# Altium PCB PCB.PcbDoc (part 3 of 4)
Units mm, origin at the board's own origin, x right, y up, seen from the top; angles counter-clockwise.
Board outline 430 x 130 mm, 2 copper layers (Top Layer, Bottom Layer); 471 components, 267 nets, 1806 pads, 471 vias.
Unrouted connection lines stored in the file: 127.
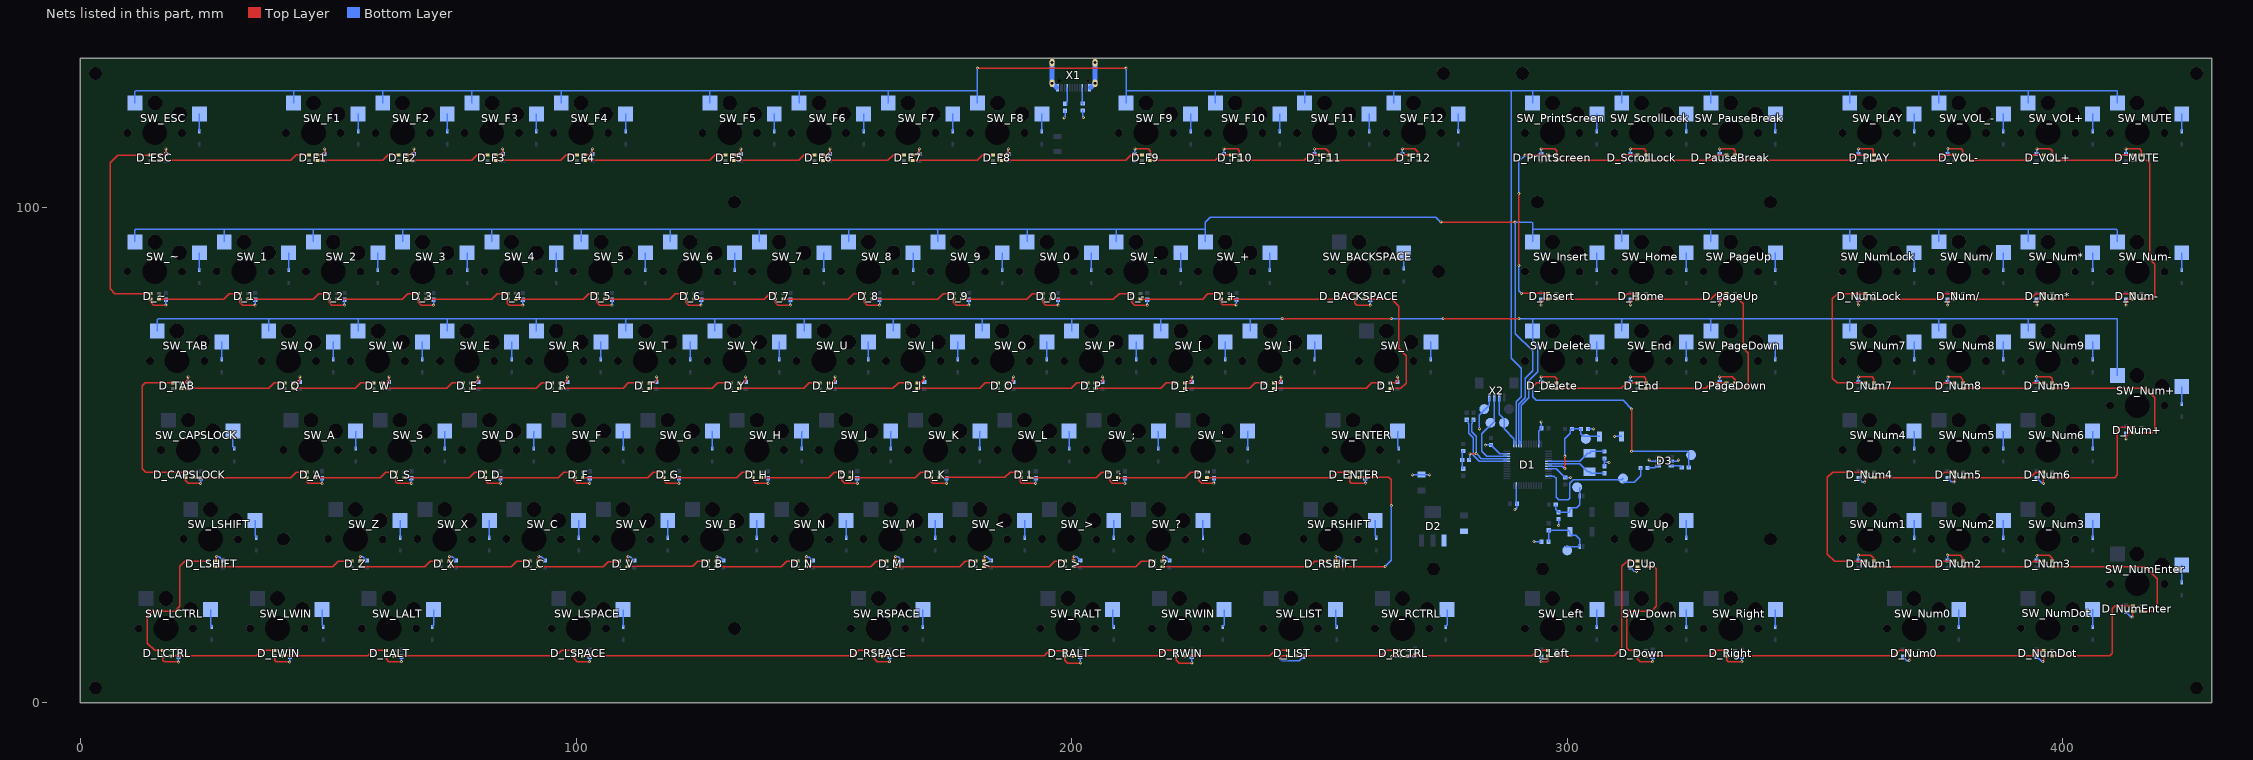
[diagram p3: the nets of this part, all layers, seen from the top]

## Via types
v1: diameter 0.6, hole 0.3, Top Layer to Bottom Layer, tented both sides, 471 vias

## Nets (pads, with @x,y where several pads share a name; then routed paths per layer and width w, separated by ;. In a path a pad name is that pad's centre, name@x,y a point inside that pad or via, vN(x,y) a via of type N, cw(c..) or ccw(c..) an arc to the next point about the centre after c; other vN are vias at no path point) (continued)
GND: C1.1 C2.1 C3.1 C4.1 C5.1 C6.1 C7.2 C8.2 C9.1 C10.1 C11.1 C12.1 C13.1 C14.1 C15.1 C16.1 C17.1 C18.1 C19.1 C20.1 C21.1 C22.1 C23.1 C24.1 C25.1 C26.1 C27.1 C28.1 C29.1 C30.1 C31.1 C32.1 C33.1 C34.1 C35.1 C36.1 C37.1 C38.1 C39.1 C40.1 C41.1 C42.1 C43.1 C44.1 C45.1 C46.1 C47.1 C48.1 C49.1 C50.1 C51.1 C52.1 C53.1 C54.1 C55.1 C56.1 C57.1 C58.1 C59.1 C60.1 C61.1 C62.1 C63.1 C64.1 C65.1 C66.1 C67.1 C68.1 C69.1 C70.1 C71.1 C72.1 C73.1 C74.1 C75.1 C76.1 C77.1 C78.1 C79.1 C80.1 C81.1 C82.1 C83.1 C84.1 C85.1 C86.1 C87.1 C88.1 C89.1 C90.1 C91.1 C92.1 C93.1 C94.1 C95.1 C96.1 C97.1 C98.1 C99.1 C100.1 C101.1 C102.1 C103.1 C104.1 C105.1 C106.1 C107.1 C108.1 C109.1 C110.1 C111.1 C112.1 C113.1 C114.1 C115.1 C116.1 C117.1 C118.1 D1.8 D1.23 D1.35 D1.47 D2.1 D3.2 D3.5 D_0.2 D_1.2 D_2.2 D_3.2 D_4.2 D_5.2 D_6.2 D_7.2 D_8.2 D_9.2 D_'.2 D_+.2 D_-.2 D_;.2 D_<.2 D_>.2 D_?.2 D_[.2 D_\.2 D_].2 D_A.2 D_B.2 D_BACKSPACE.2 D_C.2 D_CAPSLOCK.2 D_D.2 D_Delete.2 D_Down.2 D_E.2 D_End.2 D_ENTER.2 D_ESC.2 D_F1.2 D_F2.2 D_F3.2 D_F4.2 D_F5.2 D_F6.2 D_F7.2 D_F8.2 D_F9.2 D_F10.2 D_F11.2 D_F12.2 D_F.2 D_G.2 D_H.2 D_Home.2 D_I.2 D_Insert.2 D_J.2 D_K.2 D_L.2 D_LALT.2 D_LCTRL.2 D_Left.2 D_LIST.2 D_LSHIFT.2 D_LSPACE.2 D_LWIN.2 D_M.2 D_MUTE.2 D_N.2 D_Num0.2 D_Num1.2 D_Num2.2 D_Num3.2 D_Num4.2 D_Num5.2 D_Num6.2 D_Num7.2 D_Num8.2 D_Num9.2 D_Num*.2 D_Num+.2 D_Num-.2 D_Num/.2 D_NumDot.2 D_NumEnter.2 D_NumLock.2 D_O.2 D_P.2 D_PageDown.2 D_PageUp.2 D_PauseBreak.2 D_PLAY.2 D_PrintScreen.2 D_Q.2 D_R.2 D_RALT.2 D_RCTRL.2 D_Right.2 D_RSHIFT.2 D_RSPACE.2 D_RWIN.2 D_S.2 D_ScrollLock.2 D_T.2 D_TAB.2 D_U.2 D_Up.2 D_V.2 D_VOL+.2 D_VOL-.2 D_W.2 D_X.2 D_Y.2 D_Z.2 D_~.2 pad.3@283.25,59.25 R1.1 R2.1 R10.2 R11.2 SW3.2 X1.GND1 X1.GND2 X2.1 | length 500.9
  Top Layer w0.254: D_~.2@14.15,81.44 14.15,80.85 14.75,80.25 v1(17.25,80.25) ; D_ESC.2@15.85,110.56 16.81,110.56 17.25,111 v1(17.25,111.75) ; D_LCTRL.2@16.59,9.5 D_LCTRL.2@16.65,9.44 16.65,8.6 17,8.25 19.711,8.25 v1(19.746,8.216) ; D_TAB.2@20.35,64.56 21.06,64.56 21.721,65.221 v1(21.721,65.777) ; D_CAPSLOCK.2@21.15,45.44 21.15,44.85 21.714,44.286 v1(24.241,44.286) ; D_LSHIFT.2@27.35,28.56 27.35,29.35 v1@27.5,29.5 ; D_1.2@32.15,81.44 32.15,80.85 32.75,80.25 v1(35.25,80.25) ; D_LWIN.2@39.15,9.44 39.15,8.6 39.5,8.25 v1@42.25,8.25 ; D_Q.2@42.85,64.56 43.81,64.56 44.25,65 v1(44.25,65.75) ; D_A.2@45.65,45.44 45.65,44.6 45.964,44.286 v1(48.741,44.286) ; D_F1.2@47.85,110.56 48.81,110.56 49.25,111 v1(49.25,111.75) ; D_2.2@50.15,81.44 50.15,80.85 50.75,80.25 v1(53.25,80.25) ; D_Z.2@56.35,28.56 56.35,29.35 v1@56.5,29.5 ; D_W.2@60.85,64.56 61.81,64.56 62.25,65 62.25,65.718 v1(62.275,65.743) ; D_LALT.2@61.65,9.44 61.65,8.85 62.25,8.25 v1@64.75,8.25 ; D_S.2@63.65,45.44 63.65,44.6 63.964,44.286 v1(66.741,44.286) ; D_F2.2@65.85,110.56 66.81,110.56 67.25,111 v1(67.25,111.75) ; D_3.2@68.15,81.44 68.15,80.85 68.75,80.25 v1(71.25,80.25) ; D_X.2@74.35,28.56 74.35,29.35 v1@74.5,29.5 ; D_E.2@78.85,64.56 79.81,64.56 80.25,65 v1(80.25,65.75) ; D_D.2@81.65,45.44 81.65,44.85 82.214,44.286 v1(84.741,44.286) ; D_F3.2@83.85,110.56 84.81,110.56 85.201,110.951 v1(85.201,111.75) ; D_4.2@86.15,81.44 86.15,80.6 86.5,80.25 89.238,80.25 v1(89.264,80.224) ; D_C.2@92.35,28.56 92.35,29.35 v1@92.5,29.5 ; D_R.2@96.85,64.56 97.81,64.56 98.25,65 v1(98.25,65.75) ; D_LSPACE.2@99.65,9.44 99.65,8.85 100.25,8.25 v1@102.75,8.25 ; D_F.2@99.65,45.44 99.65,44.85 100.214,44.286 v1(102.741,44.286) ; D_F4.2@101.85,110.56 102.81,110.56 103.25,111 103.25,111.725 v1(103.275,111.75) ; D_5.2@104.15,81.44 104.15,80.85 104.75,80.25 v1(107.25,80.25) ; D_V.2@110.35,28.56 110.35,29.35 v1@110.5,29.5 ; D_T.2@114.85,64.56 115.81,64.56 116.25,65 v1(116.25,65.75) ; D_G.2@117.65,45.44 117.65,44.85 118.214,44.286 v1(120.741,44.286) ; D_6.2@122.15,81.44 122.15,80.85 122.75,80.25 v1(125.25,80.25) ; D_B.2@128.35,28.56 128.35,29.35 v1@128.5,29.5 ; D_F5.2@131.85,110.56 132.81,110.56 133.25,111 v1(133.25,111.75) ; D_Y.2@132.85,64.56 133.81,64.56 134.221,64.971 v1(134.221,65.762) ; D_H.2@135.65,45.44 135.65,44.85 136.214,44.286 v1(138.741,44.286) ; D_7.2@140.15,81.44 140.15,80.85 140.75,80.25 v1(143.25,80.25) ; D_N.2@146.35,28.56 146.35,29.35 v1@146.5,29.5 ; D_F6.2@149.85,110.56 150.81,110.56 151.25,111 v1(151.25,111.75) ; D_U.2@150.85,64.56 151.81,64.56 152.25,65 v1(152.25,65.75) ; D_J.2@153.65,45.44 153.65,44.85 154.214,44.286 v1(156.741,44.286) ; D_8.2@158.15,81.44 158.15,80.85 158.75,80.25 v1(161.25,80.25) ; D_RSPACE.2@160.15,9.44 160.15,8.85 160.75,8.25 v1@163.25,8.25 ; D_M.2@164.35,28.56 164.35,29.35 v1@164.5,29.5 ; D_F7.2@167.85,110.56 168.81,110.56 169.25,111 v1(169.25,111.75) ; D_I.2@168.85,64.56 169.56,64.56 170.25,65.25 v1(170.25,65.75) ; D_K.2@171.65,45.44 171.65,44.6 171.964,44.286 v1(174.741,44.286) ; D_9.2@176.15,81.44 176.15,80.85 176.75,80.25 179.236,80.25 v1(179.264,80.222) ; D_<.2@182.35,28.56 182.35,29.213 182.541,29.404 v1(182.541,29.497) ; D_F8.2@185.85,110.56 186.81,110.56 187.25,111 v1(187.25,111.75) ; D_O.2@186.85,64.56 187.81,64.56 188.25,65 v1(188.25,65.75) ; D_L.2@189.65,45.44 189.65,44.6 189.964,44.286 v1(192.741,44.286) ; D_0.2@194.15,81.44 194.15,80.85 194.75,80.25 v1(197.25,80.25) ; D_RALT.2@198.65,9.44 198.65,8.6 199.25,8 v1@201.75,8 ; D_>.2@200.35,28.56 200.35,29.35 v1@200.5,29.5 ; D_P.2@204.85,64.56 205.81,64.56 206.25,65 v1(206.25,65.739) ; 207.65,45.44 207.65,44.85 208.214,44.286 v1(210.741,44.286) ; D_-.2@212.15,81.44 212.15,80.85 212.75,80.25 v1(215.25,80.25) ; v1(212.75,111.75) 215.5,111.75 215.85,111.4 D_F9.2@215.85,110.56 ; D_?.2@218.35,28.56 218.35,29.242 218.505,29.397 v1(218.505,29.49) ; D_RWIN.2@221.15,9.44 221.15,8.6 221.75,8 v1@224.25,8 ; D_[.2@222.85,64.56 223.81,64.56 224.25,65 v1(224.25,65.75) ; D_'.2@225.65,45.44 225.65,44.85 226.202,44.298 v1(228.688,44.298) ; D_+.2@230.15,81.44 230.15,80.6 230.473,80.277 v1(233.188,80.277) ; v1(230.725,111.75) 233.5,111.75 233.85,111.4 D_F10.2@233.85,110.56 ; D_].2@240.85,64.56 241.81,64.56 242.25,65 v1(242.25,65.75) ; v1(241.991,9.036) 242.084,9.036 242.488,9.44 D_LIST.2@243.65,9.44 ; v1(249,111.75) 251.25,111.75 251.85,111.15 D_F11.2@251.85,110.56 ; v1@253.25,29.5 253.35,29.4 D_RSHIFT.2@253.35,28.56 ; D_ENTER.2@256.15,45.44 256.15,44.6 256.445,44.305 v1(259.283,44.305) ; D_BACKSPACE.2@257.15,81.44 257.15,80.6 257.5,80.25 v1(260.25,80.25) ; D_\.2@264.35,64.56 265.31,64.56 265.75,65 v1(265.75,65.75) ; v1@264.5,9.25 264.69,9.44 D_RCTRL.2@266.15,9.44 ; v1(266.75,111.75) 269.25,111.75 269.85,111.15 D_F12.2@269.85,110.56 ; v1(294.725,80.258) 294.75,80.284 294.75,81 295.19,81.44 D_Insert.2@296.15,81.44 ; v1@294.75,8.25 296,8.25 296.15,8.4 D_Left.2@296.15,9.44 ; v1(294.75,65.75) 297.5,65.75 297.85,65.4 D_Delete.2@297.85,64.56 ; v1(294.75,111.75) 297.5,111.75 297.85,111.4 D_PrintScreen.2@297.85,110.56 ; v1(312.744,80.272) 312.744,80.994 313.19,81.44 D_Home.2@314.15,81.44 ; v1(312.747,111.752) 312.749,111.75 315.5,111.75 315.85,111.4 D_ScrollLock.2@315.85,110.56 ; v1(312.75,65.75) 315.5,65.75 315.85,65.4 D_End.2@315.85,64.56 ; v1@314,26.5 314.15,26.65 D_Up.2@314.15,27.44 ; D_Down.2@314.09,9.5 D_Down.2@314.15,9.44 314.15,8.85 314.75,8.25 v1@317.25,8.25 ; v1(330.75,65.75) 333.25,65.75 333.85,65.15 D_PageDown.2@333.85,64.56 ; v1(330.75,80.25) 330.75,81 331.19,81.44 D_PageUp.2@332.15,81.44 ; v1(330.75,111.75) 333.5,111.75 333.85,111.4 D_PauseBreak.2@333.85,110.56 ; D_Right.2@332.15,9.44 332.15,8.6 332.5,8.25 v1@335.25,8.25 ; v1(358.741,29.786) 361.214,29.786 361.85,29.15 D_Num1.2@361.85,28.56 ; v1(358.75,65.75) 361.5,65.75 361.85,65.4 D_Num7.2@361.85,64.56 ; v1(358.75,80.25) 358.75,81 359.19,81.44 D_NumLock.2@360.15,81.44 ; v1(358.75,111.75) 361.5,111.75 361.75,111.5 361.75,110.66 D_PLAY.2@361.85,110.56 ; v1(359.991,44.536) 359.991,44.63 360.15,44.789 D_Num4.2@360.15,45.44 ; v1@369,8.5 369.15,8.65 D_Num0.2@369.15,9.44 ; v1@376.75,29.75 379.25,29.75 379.85,29.15 D_Num2.2@379.85,28.56 ; v1@376.75,65.75 379.25,65.75 379.85,65.15 D_Num8.2@379.85,64.56 ; v1(376.75,80.25) 376.75,81 377.19,81.44 D_Num/.2@378.15,81.44 ; v1(376.789,111.79) 376.829,111.75 379.5,111.75 379.85,111.4 D_VOL-.2@379.85,110.56 ; v1@378,44.5 378.15,44.65 D_Num5.2@378.15,45.44 ; v1@394.75,65.75 397.5,65.75 397.85,65.4 D_Num9.2@397.85,64.56 ; v1(394.75,80.25) 394.75,81 395.19,81.44 D_Num*.2@396.15,81.44 ; v1(394.75,111.75) 397.5,111.75 397.85,111.4 D_VOL+.2@397.85,110.56 ; v1(394.774,29.745) 397.255,29.745 397.85,29.15 D_Num3.2@397.85,28.56 ; v1@396,8.25 396.15,8.4 D_NumDot.2@396.15,9.44 ; v1(396.068,44.246) 396.068,45.358 D_Num6.2@396.15,45.44 ; v1(412.705,111.751) v1(412.705,111.751) 415.5,111.75 415.85,111.4 D_MUTE.2@415.85,110.56 ; v1(412.75,53.25) 412.75,53.75 413.44,54.44 D_Num+.2@414.15,54.44 ; v1(412.75,80.25) 412.75,81 413.19,81.44 D_Num-.2@414.15,81.44 ; v1@414,17.25 414.15,17.4 D_NumEnter.2@414.15,18.44
  Bottom Layer w0.254: v1(17.25,80.25) C93.1@17.25,81.3 ; C109.1@17.25,110.7 17.296,110.746 17.296,111.704 v1(17.25,111.75) ; v1@19.75,8.25 C30.1@19.75,9.3 ; C108.1@21.75,64.7 v1@21.75,65.777 ; v1@24.25,44.25 C62.1@24.25,45.3 ; v1(27.491,29.536) 27.557,29.47 27.98,29.47 C31.1@28.75,28.7 ; v1(35.25,80.25) C94.1@35.25,81.3 ; v1@42.25,8.25 C33.1@42.25,9.3 ; C69.1@44.25,64.7 v1(44.25,65.75) ; v1@48.75,44.25 C63.1@48.75,45.3 ; C110.1@49.25,110.7 v1(49.25,111.75) ; v1(53.25,80.25) C95.1@53.25,81.3 ; v1(56.491,29.536) 56.557,29.47 56.98,29.47 C32.1@57.75,28.7 ; C64.1@62.25,64.7 v1@62.25,65.75 ; v1@64.75,8.25 C34.1@64.75,9.3 ; v1@66.75,44.25 C65.1@66.75,45.3 ; C111.1@67.25,110.7 67.24,110.71 67.25,110.72 v1(67.25,111.75) ; v1(71.25,80.25) C61.1@71.25,81.3 ; v1(74.491,29.536) 74.557,29.47 74.98,29.47 C36.1@75.75,28.7 ; C67.1@80.25,64.7 v1(80.25,65.75) ; v1@84.75,44.25 C66.1@84.75,45.3 ; v1(85.201,111.75) 85.25,111.701 C112.1@85.25,110.7 ; v1@89.25,80.25 C96.1@89.25,81.3 ; v1(92.491,29.536) 92.557,29.47 92.98,29.47 C37.1@93.75,28.7 ; C68.1@98.25,64.7 v1(98.25,65.75) ; v1@102.75,8.25 C35.1@102.75,9.3 ; v1@102.75,44.25 C29.1@102.75,45.3 ; C113.1@103.25,110.7 103.275,110.725 v1(103.275,111.75) ; v1(107.25,80.25) C97.1@107.25,81.3 ; v1(110.491,29.536) 110.557,29.47 110.98,29.47 C38.1@111.75,28.7 ; C42.1@116.25,64.7 v1(116.25,65.75) ; v1@120.75,44.25 C41.1@120.75,45.3 ; v1(125.25,80.25) C100.1@125.25,81.3 ; v1(128.416,29.461) 128.482,29.395 129.055,29.395 C39.1@129.75,28.7 ; C114.1@133.25,110.7 v1(133.25,111.75) ; C43.1@134.25,64.7 v1@134.25,65.75 ; v1@138.75,44.25 C44.1@138.75,45.3 ; v1(143.25,80.25) C101.1@143.25,81.3 ; v1(146.502,29.469) 146.569,29.403 147.047,29.403 C40.1@147.75,28.7 ; C115.1@151.25,110.7 v1(151.25,111.75) ; C46.1@152.25,64.7 v1(152.25,65.75) ; v1@156.75,44.25 C70.1@156.75,45.3 ; v1(161.25,80.25) C102.1@161.25,81.3 ; v1@163.25,8.25 C47.1@163.25,9.3 ; v1(164.468,29.534) 164.534,29.467 164.983,29.467 C45.1@165.75,28.7 ; C116.1@169.25,110.7 v1(169.25,111.75) ; C71.1@170.25,64.7 v1(170.25,65.75) ; v1@174.75,44.25 C72.1@174.75,45.3 ; v1@179.25,80.25 C103.1@179.25,81.3 ; v1@182.541,29.5 182.95,29.5 C75.1@183.75,28.7 ; C117.1@187.25,110.7 v1(187.25,111.75) ; C73.1@188.25,64.7 v1(188.25,65.75) ; v1@192.75,44.25 C74.1@192.75,45.3 ; v1(197.25,80.25) C104.1@197.25,81.3 ; v1(198.5,118) 198.675,118.175 R1.1@198.675,119.475 ; v1(200.491,29.536) 200.557,29.47 200.98,29.47 C77.1@201.75,28.7 ; v1@201.75,8 C76.1@201.75,9.3 ; R2.1@202.225,119.525 202.225,118.275 v1@202.5,118 ; C48.1@206.25,64.7 v1@206.25,65.75 ; v1@210.75,44.25 C10.1@210.75,45.3 ; C89.1@212.75,110.7 v1(212.75,111.75) ; v1(215.25,80.25) C105.1@215.25,81.3 ; v1@218.505,29.5 218.95,29.5 C13.1@219.75,28.7 ; v1@224.25,8 C14.1@224.25,9.3 ; C98.1@224.25,64.7 v1(224.25,65.75) ; v1@228.75,44.25 C12.1@228.75,45.3 ; v1(230.725,111.75) 230.725,110.725 C90.1@230.75,110.7 ; v1@233.25,80.25 C106.1@233.25,81.3 ; v1@242,9 242.5,8.5 245.95,8.5 C78.1@246.75,9.3 ; C99.1@242.25,64.7 v1(242.25,65.75) ; C91.1@249,110.7 v1(249,111.75) ; v1(253.291,29.486) 253.299,29.478 253.972,29.478 C80.1@254.75,28.7 ; v1@259.25,44.25 C9.1@259.25,45.3 ; v1(260.25,80.25) C107.1@260.25,81.3 ; v1(264.491,9.286) 268.986,9.286 C79.1@269.25,9.55 ; C60.1@265.75,64.7 v1(265.75,65.75) ; C92.1@266.75,110.7 v1(266.75,111.75) ; v1@268.75,46.05 C7.2@270.55,46.05 270.6,46 v1@272,46 ; v1(282.25,55.25) 282.25,58 284.25,60 X2.1@284.25,61.6 ; v1(283.502,52.001) 283.525,52.025 C6.1@284.625,52.025 285.275,51.375 286.391,50.259 287.791,50.259 D1.35@287.8,50.25 ; v1@289.5,39 289.85,39.35 C5.1@289.85,40.15 289.75,40.25 D1.23@289.75,43.8 ; v1(293.25,32.5) R11.2@294.8,32.5 ; D1.47@294.25,52.2 294.25,54.825 C3.1@294.8,55.375 v1@294.8,56.7 ; v1(294.729,8.292) 294.729,9.279 C83.1@294.75,9.3 ; C87.1@294.75,64.7 v1(294.75,65.75) ; v1@294.75,80.25 C82.1@294.75,81.3 ; C11.1@294.75,110.7 v1(294.75,111.75) ; D1.8@296.2,47.25 297.775,47.25 C4.1@299.575,45.45 v1@300.7,45.45 ; v1(298.25,35.75) R10.2@298.25,37.05 ; C118.1@304.2,55.25 v1(305.25,55.25) ; C1.1@307.5,47.7 307.5,48.5 ; C2.1@307.5,49.3 307.5,48.5 ; v1@308.5,48.5 307.5,48.5 ; v1(309.5,53.75) SW3.2@310.95,53.75 ; C86.1@312.75,27.3 313.497,26.553 313.893,26.553 v1(313.959,26.487) ; C88.1@312.75,64.7 v1(312.75,65.75) ; v1@312.75,80.25 C15.1@312.75,81.3 ; C81.1@312.75,110.7 v1@312.75,111.75 ; v1(316.5,49) 316.752,48.748 D3.5@318.346,48.748 D3.5@318.373,48.775 ; v1@317.25,8.25 C84.1@317.25,9.3 ; D3.2@320.946,48.748 322.248,48.748 v1@322.5,49 ; C49.1@330.75,64.7 v1(330.75,65.75) ; v1(330.75,80.25) C18.1@330.75,81.3 ; C16.1@330.75,110.7 v1(330.75,111.75) ; v1@335.25,8.25 C85.1@335.25,9.3 ; C55.1@358.75,28.7 v1@358.75,29.75 ; C26.1@358.75,45.3 359.55,44.5 v1@359.991,44.5 ; C23.1@358.75,64.7 v1(358.75,65.75) ; v1(358.75,80.25) C19.1@358.75,81.3 ; C50.1@358.75,110.7 v1(358.75,111.75) ; C17.1@367.75,9.3 368.55,8.5 v1@369,8.5 ; C56.1@376.75,28.7 v1@376.75,29.75 ; C27.1@376.75,45.3 377.447,44.603 377.925,44.603 v1(377.991,44.536) ; C24.1@376.75,64.7 v1@376.75,65.75 ; v1(376.75,80.25) C20.1@376.75,81.3 ; C51.1@376.75,110.7 v1@376.75,111.75 ; C58.1@394.75,9.3 395.8,8.25 v1@396,8.25 ; C57.1@394.75,28.7 v1@394.75,29.75 ; C28.1@394.75,45.3 395.8,44.25 v1@396,44.25 ; C25.1@394.75,64.7 v1@394.75,65.75 ; v1(394.75,80.25) C21.1@394.75,81.3 ; C52.1@394.75,110.7 v1(394.75,111.75) ; C59.1@412.75,18.3 413.8,17.25 v1@414,17.25 ; v1(412.75,53.25) C54.1@412.75,54.3 ; v1(412.75,80.25) C22.1@412.75,81.3 ; C53.1@412.75,110.7 v1@412.75,111.75
  other v1: 201.741,8.036 224.241,8.036 42.213,8.203 163.228,8.273 64.741,8.286 102.699,8.298 317.241,8.286 335.241,8.286 395.991,8.286 368.98,8.494 413.991,17.286 376.698,29.792 289.453,39.009 300.678,45.484 268.75,46 272.25,46 308.453,48.509 322.453,49.009 294.744,56.679 376.786,65.707 394.721,65.785 202.363,118.138
JTCK: D1.37 pad.3@287.25,56.5 X2.3 | length 10.6
  Bottom Layer w0.254: X2.3@286.25,61.6 286.25,58.25 287.25,57.25 287.25,55.25 289.25,53.25 D1.37@289.25,52.2
JTMS: D1.34 pad.3@284.5,56.5 X2.2 | length 17.3
  Bottom Layer w0.254: X2.2@285.25,61.6 285.25,56.75 282.75,54.25 282.75,50.75 283.75,49.75 D1.34@287.8,49.75
LEDs_3.3: D1.11 pad.3@311.25,45.25 R5.2 | length 28.4
  Bottom Layer w0.254: D1.11@296.2,45.75 297.25,45.75 297.75,45.25 297.75,41.5 298.25,41 300.25,41 300.5,41.25 300.5,44.25 301.25,45 311,45 pad.3@311.25,45.25 ; pad.3@311.25,44.5 313.5,44.5 314.8,45.8 R5.2@314.8,47.375
LEDs_5: D_Delete.3 pad.3@325,50 R6.1 | length 49.7
  Top Layer w0.254: v1(293,63.75) 293.81,64.56 D_Delete.3@296.15,64.56 ; v1(313,50.75) v1(313,59.25)
  Bottom Layer w0.254: v1(293,63.75) 293,61.75 293.75,61 311.25,61 v1(313,59.25) ; v1(313,50.75) 324.25,50.75 324.525,50.475 R6.1@324.525,47.45 R6.1@324.528,47.447
NetC1_2: C1.2 D1.6 Z1.1 | length 12.1
  Bottom Layer w0.254: D1.6@296.2,48.25 302.55,48.25 304.15,46.65 Z1.1@304.5,46.65 304.85,46.3 C1.2@307.5,46.3
NetC2_2: C2.2 D1.5 Z1.2 | length 12.1
  Bottom Layer w0.254: D1.5@296.2,48.75 302.55,48.75 304.15,50.35 Z1.2@304.5,50.35 304.85,50.7 C2.2@307.5,50.7
NetD1_32: D1.32 R4.2 | length 15.2
  Bottom Layer w0.254: R4.2@279.575,56.975 R4.2@279.7,57.1 279.998,56.802 279.998,56.402 280.1,56.3 280.1,54.4 281,53.5 281,49.95 282.2,48.75 D1.32@287.8,48.75
NetD1_33: D1.33 R3.2 R12.1 | length 16.6
  Top Layer w0.254: v1(280.35,50.225) 280.375,50.25 281.6,50.25 v1(281.625,50.275)
  Bottom Layer w0.254: R12.1@280.2,49 280.35,49.15 v1(280.35,50.225) v1@280.3,50.275 ; R3.2@281.1,57.1 280.802,56.802 280.802,56.402 280.7,56.3 280.7,54.7 281.625,53.775 v1(281.625,50.275) 281.8,50.1 282.65,49.25 D1.33@287.8,49.25
NetD3_3: D3.3 R6.2 | length 2.3
  Bottom Layer w0.254: D3.3@320.946,47.798 322.777,47.798 R6.2@323.125,47.45
NetD3_4: D3.4 R5.1 | length 2.3
  Bottom Layer w0.254: R5.1@316.2,47.375 317.673,47.375 318.096,47.798 D3.4@318.346,47.798
NetD_0_1: D_0.1 D_9.3 | length 16.8
  Top Layer w0.254: D_9.3@177.85,81.44 190.94,81.44 192.06,82.56 D_0.1@194.15,82.56
NetD_0_3: D_0.3 D_-.1 | length 16.8
  Top Layer w0.254: D_0.3@195.85,81.44 208.44,81.44 209.56,82.56 D_-.1@212.15,82.56
NetD_1_1: D_1.1 D_~.3 | length 16.8
  Top Layer w0.254: D_~.3@15.85,81.44 28.94,81.44 30.06,82.56 D_1.1@32.15,82.56
NetD_1_3: D_1.3 D_2.1 | length 16.8
  Top Layer w0.254: D_1.3@33.85,81.44 46.94,81.44 48.06,82.56 D_2.1@50.15,82.56
NetD_2_3: D_2.3 D_3.1 | length 16.8
  Top Layer w0.254: D_2.3@51.85,81.44 64.94,81.44 66.06,82.56 D_3.1@68.15,82.56
NetD_3_3: D_3.3 D_4.1 | length 16.8
  Top Layer w0.254: D_3.3@69.85,81.44 82.94,81.44 84.06,82.56 D_4.1@86.15,82.56
NetD_4_3: D_4.3 D_5.1 | length 16.8
  Top Layer w0.254: D_4.3@87.85,81.44 101.44,81.44 102.56,82.56 D_5.1@104.15,82.56
NetD_5_3: D_5.3 D_6.1 | length 16.8
  Top Layer w0.254: D_5.3@105.85,81.44 118.94,81.44 120.06,82.56 D_6.1@122.15,82.56
NetD_6_3: D_6.3 D_7.1 | length 16.8
  Top Layer w0.254: D_6.3@123.85,81.44 137.94,81.44 139.06,82.56 D_7.1@140.15,82.56
NetD_7_3: D_7.3 D_8.1 | length 16.8
  Top Layer w0.254: D_7.3@141.85,81.44 154.94,81.44 156.06,82.56 D_8.1@158.15,82.56
NetD_8_3: D_8.3 D_9.1 | length 16.8
  Top Layer w0.254: D_8.3@159.85,81.44 172.94,81.44 174.06,82.56 D_9.1@176.15,82.56
NetD_'_1: D_'.1 D_;.3 | length 16.8
  Top Layer w0.254: 209.35,45.44 222.94,45.44 224.06,46.56 D_'.1@225.65,46.56
NetD_'_3: D_'.3 D_ENTER.1 | length 29.3
  Top Layer w0.254: D_'.3@227.35,45.44 252.44,45.44 253.56,46.56 D_ENTER.1@256.15,46.56
NetD_+_1: D_+.1 D_-.3 | length 16.8
  Top Layer w0.254: D_-.3@213.85,81.44 226.44,81.44 227.5,82.5 230.09,82.5 D_+.1@230.15,82.56
NetD_+_3: D_+.3 D_BACKSPACE.1 | length 25.8
  Top Layer w0.254: D_+.3@231.85,81.44 254.44,81.44 255.56,82.56 D_BACKSPACE.1@257.15,82.56
NetD_;_1: D_;.1 D_L.3 | length 16.8
  Top Layer w0.254: D_L.3@191.35,45.44 204.94,45.44 206.06,46.56 207.65,46.56
NetD_<_1: D_<.1 D_>.3 | length 16.8
  Top Layer w0.254: D_<.1@182.35,27.44 195.44,27.44 196.56,28.56 D_>.3@198.65,28.56
NetD_<_3: D_<.3 D_M.1 | length 16.8
  Top Layer w0.254: D_M.1@164.35,27.44 177.44,27.44 178.56,28.56 D_<.3@180.65,28.56
NetD_>_1: D_>.1 D_?.3 | length 16.8
  Top Layer w0.254: D_>.1@200.35,27.44 212.94,27.44 214.06,28.56 D_?.3@216.65,28.56
NetD_?_1: D_?.1 D_RSHIFT.3 | length 33.8
  Top Layer w0.254: D_?.1@218.35,27.44 247.94,27.44 249.06,28.56 D_RSHIFT.3@251.65,28.56
NetD_[_1: D_[.1 D_].3 | length 16.8
  Top Layer w0.254: D_[.1@222.85,63.44 235.94,63.44 237.06,64.56 D_].3@239.15,64.56
NetD_[_3: D_[.3 D_P.1 | length 16.8
  Top Layer w0.254: D_P.1@204.85,63.44 217.94,63.44 219.06,64.56 D_[.3@221.15,64.56
NetD_\_1: D_\.1 D_BACKSPACE.3 | length 27.5
  Top Layer w0.254: D_BACKSPACE.3@258.85,81.44 264.56,81.44 266,80 266,71.5 267.5,70 267.5,64.5 266.44,63.44 D_\.1@264.35,63.44
NetD_\_3: D_\.3 D_].1 | length 22.3
  Top Layer w0.254: D_].1@240.85,63.44 259.44,63.44 260.56,64.56 D_\.3@262.65,64.56
NetD_A_1: D_A.1 D_CAPSLOCK.3 | length 23.3
  Top Layer w0.254: D_CAPSLOCK.3@22.85,45.44 42.44,45.44 43.56,46.56 D_A.1@45.65,46.56
NetD_A_3: D_A.3 D_S.1 | length 16.8
  Top Layer w0.254: D_A.3@47.35,45.44 60.44,45.44 61.56,46.56 D_S.1@63.65,46.56
NetD_B_1: D_B.1 D_N.3 | length 16.8
  Top Layer w0.254: D_B.1@128.35,27.44 141.44,27.44 142.56,28.56 D_N.3@144.65,28.56
NetD_B_3: D_B.3 D_V.1 | length 16.8
  Top Layer w0.254: D_V.1@110.35,27.44 110.41,27.5 123.5,27.5 124.56,28.56 D_B.3@126.65,28.56
NetD_C_1: D_C.1 D_V.3 | length 16.8
  Top Layer w0.254: D_C.1@92.35,27.44 105.44,27.44 106.5,28.5 108.59,28.5 D_V.3@108.65,28.56
NetD_C_3: D_C.3 D_X.1 | length 16.8
  Top Layer w0.254: D_X.1@74.35,27.44 86.94,27.44 88.06,28.56 D_C.3@90.65,28.56
NetD_CAPSLOCK_1: D_CAPSLOCK.1 D_TAB.3 | length 32.1
  Top Layer w0.254: D_TAB.3@18.65,64.56 13.06,64.56 12.5,64 12.5,47.25 13.19,46.56 D_CAPSLOCK.1@21.15,46.56
NetD_D_1: D_D.1 D_S.3 | length 16.8
  Top Layer w0.254: D_S.3@65.35,45.44 78.44,45.44 79.56,46.56 D_D.1@81.65,46.56
NetD_D_3: D_D.3 D_F.1 | length 16.8
  Top Layer w0.254: D_D.3@83.35,45.44 96.44,45.44 97.56,46.56 D_F.1@99.65,46.56
NetD_Delete_1: D_Delete.1 D_End.3 | length 16.8
  Top Layer w0.254: D_Delete.1@297.85,63.44 310.94,63.44 312.06,64.56 D_End.3@314.15,64.56
NetD_Down_1: D_Down.1 D_Up.3 | length 25.8
  Top Layer w0.254: D_Down.1@314.15,10.56 312.44,10.56 312,11 312,18 312.5,18.5 317,18.5 318,19.5 318,27 317.56,27.44 D_Up.3@315.85,27.44
NetD_Down_3: D_Down.3 D_Right.1 | length 16.8
  Top Layer w0.254: D_Down.3@315.85,9.44 328.94,9.44 330.06,10.56 D_Right.1@332.15,10.56
NetD_E_1: D_E.1 D_R.3 | length 16.8
  Top Layer w0.254: D_E.1@78.85,63.44 91.94,63.44 93.06,64.56 D_R.3@95.15,64.56
NetD_E_3: D_E.3 D_W.1 | length 16.8
  Top Layer w0.254: D_W.1@60.85,63.44 73.94,63.44 75.06,64.56 D_E.3@77.15,64.56
NetD_End_1: D_End.1 D_PageDown.3 | length 16.8
  Top Layer w0.254: D_End.1@315.85,63.44 327.94,63.44 329.06,64.56 D_PageDown.3@332.15,64.56
NetD_ENTER_3: D_ENTER.3 D_RSHIFT.1 | length 34.8
  Top Layer w0.254: D_RSHIFT.1@253.35,27.44 v1@263.25,27.44 ; D_ENTER.3@257.85,45.44 257.91,45.5 264,45.5 264.5,45 264.5,39.796 v1(264.491,39.786)
  Bottom Layer w0.254: v1(263.25,27.5) 264.491,28.741 v1(264.491,39.786)
NetD_ESC_1: D_ESC.1 D_F1.3 | length 30.8
  Top Layer w0.254: D_ESC.1@15.85,109.44 42.44,109.44 43.56,110.56 D_F1.3@46.15,110.56
NetD_ESC_3: D_ESC.3 D_~.1 | length 42.8
  Top Layer w0.254: D_~.1@14.15,82.56 6.94,82.56 6,83.5 6,109 7.5,110.5 14.09,110.5 D_ESC.3@14.15,110.56
NetD_F1_1: D_F1.1 D_F2.3 | length 16.8
  Top Layer w0.254: D_F1.1@47.85,109.44 47.91,109.5 61,109.5 62.06,110.56 D_F2.3@64.15,110.56
NetD_F2_1: D_F2.1 D_F3.3 | length 16.8
  Top Layer w0.254: D_F2.1@65.85,109.44 78.94,109.44 80.06,110.56 D_F3.3@82.15,110.56
NetD_F3_1: D_F3.1 D_F4.3 | length 16.8
  Top Layer w0.254: D_F3.1@83.85,109.44 96.94,109.44 98.06,110.56 D_F4.3@100.15,110.56
NetD_F4_1: D_F4.1 D_F5.3 | length 28.8
  Top Layer w0.254: D_F4.1@101.85,109.44 126.94,109.44 128.06,110.56 D_F5.3@130.15,110.56
NetD_F5_1: D_F5.1 D_F6.3 | length 16.8
  Top Layer w0.254: D_F5.1@131.85,109.44 144.94,109.44 146.06,110.56 D_F6.3@148.15,110.56
NetD_F6_1: D_F6.1 D_F7.3 | length 16.8
  Top Layer w0.254: D_F6.1@149.85,109.44 162.94,109.44 164.06,110.56 D_F7.3@166.15,110.56
NetD_F7_1: D_F7.1 D_F8.3 | length 16.8
  Top Layer w0.254: D_F7.1@167.85,109.44 180.94,109.44 182.06,110.56 D_F8.3@184.15,110.56
NetD_F8_1: D_F8.1 D_F9.3 | length 28.8
  Top Layer w0.254: D_F8.1@185.85,109.44 210.94,109.44 212.06,110.56 D_F9.3@214.15,110.56
NetD_F9_1: D_F9.1 D_F10.3 | length 16.8
  Top Layer w0.254: D_F9.1@215.85,109.44 228.94,109.44 230.06,110.56 D_F10.3@232.15,110.56
NetD_F10_1: D_F10.1 D_F11.3 | length 16.8
  Top Layer w0.254: D_F10.1@233.85,109.44 246.94,109.44 248.06,110.56 D_F11.3@250.15,110.56
NetD_F11_1: D_F11.1 D_F12.3 | length 16.8
  Top Layer w0.254: D_F11.1@251.85,109.44 251.91,109.5 265,109.5 266.06,110.56 D_F12.3@268.15,110.56
NetD_F_3: D_F.3 D_G.1 | length 16.8
  Top Layer w0.254: D_F.3@101.35,45.44 114.44,45.44 115.56,46.56 D_G.1@117.65,46.56
NetD_G_3: D_G.3 D_H.1 | length 16.8
  Top Layer w0.254: D_G.3@119.35,45.44 132.44,45.44 133.56,46.56 D_H.1@135.65,46.56
NetD_H_3: D_H.3 D_J.1 | length 16.8
  Top Layer w0.254: D_H.3@137.35,45.44 150.94,45.44 152.06,46.56 D_J.1@153.65,46.56
NetD_Home_1: D_Home.1 D_Insert.3 | length 16.8
  Top Layer w0.254: D_Insert.3@297.85,81.44 310.94,81.44 312.06,82.56 D_Home.1@314.15,82.56
NetD_Home_3: D_Home.3 D_PageUp.1 | length 16.8
  Top Layer w0.254: D_Home.3@315.85,81.44 328.94,81.44 330.06,82.56 D_PageUp.1@332.15,82.56
NetD_I_1: D_I.1 D_O.3 | length 16.8
  Top Layer w0.254: D_I.1@168.85,63.44 181.44,63.44 182.56,64.56 D_O.3@185.15,64.56
NetD_I_3: D_I.3 D_U.1 | length 16.8
  Top Layer w0.254: D_U.1@150.85,63.44 163.94,63.44 165.06,64.56 D_I.3@167.15,64.56
NetD_Insert_1: D_Insert.1 D_PrintScreen.3 | length 38.7
  Top Layer w0.254: v1(290.25,88.25) v1(290.25,102.75) ; v1(290.75,82.598) 296.112,82.598 D_Insert.1@296.15,82.56 ; v1(291.5,110.5) 296.09,110.5 D_PrintScreen.3@296.15,110.56
  Bottom Layer w0.254: v1(290.25,88.25) 290.25,83.13 290.75,82.63 v1(290.75,82.598) ; v1(290.25,102.75) 290.25,109.25 v1(291.5,110.5)
NetD_J_3: D_J.3 D_K.1 | length 16.8
  Top Layer w0.254: D_J.3@155.35,45.44 168.44,45.44 169.56,46.56 D_K.1@171.65,46.56
NetD_K_3: D_K.3 D_L.1 | length 16.8
  Top Layer w0.254: D_K.3@173.35,45.44 173.41,45.5 186.5,45.5 187.56,46.56 D_L.1@189.65,46.56
NetD_LALT_1: D_LALT.1 D_LWIN.3 | length 21.3
  Top Layer w0.254: D_LWIN.3@40.85,9.44 57.94,9.44 59.06,10.56 D_LALT.1@61.65,10.56
NetD_LALT_3: D_LALT.3 D_LSPACE.1 | length 36.8
  Top Layer w0.254: D_LALT.3@63.35,9.44 95.94,9.44 97.06,10.56 D_LSPACE.1@99.65,10.56
NetD_LCTRL_1: D_LCTRL.1 D_LSHIFT.3 | length 30.7
  Top Layer w0.254: D_LCTRL.1@16.65,10.56 14.94,10.56 13.5,12 13.5,17.5 14.5,18.5 19,18.5 20,19.5 20,27.5 21.06,28.56 D_LSHIFT.3@25.65,28.56
NetD_LCTRL_3: D_LCTRL.3 D_LWIN.1 | length 21.3
  Top Layer w0.254: D_LCTRL.3@18.35,9.44 35.44,9.44 36.56,10.56 D_LWIN.1@39.15,10.56
NetD_Left_1: D_Left.1 D_RCTRL.3 | length 28.8
  Top Layer w0.254: D_RCTRL.3@267.85,9.44 292.94,9.44 294.06,10.56 D_Left.1@296.15,10.56
NetD_Left_3: D_Left.3 D_Up.1 | length 33.9
  Top Layer w0.254: D_Left.3@297.85,9.44 309.44,9.44 311,11 311,27.5 312.06,28.56 D_Up.1@314.15,28.56
NetD_LIST_1: D_LIST.1 D_RWIN.3 | length 21.3
  Top Layer w0.254: D_RWIN.3@222.85,9.44 239.94,9.44 241.06,10.56 D_LIST.1@243.65,10.56
NetD_LIST_3: D_LIST.3 D_RCTRL.1 | length 21.3
  Top Layer w0.254: D_LIST.3@245.35,9.44 262.44,9.44 263.56,10.56 D_RCTRL.1@266.15,10.56
NetD_LSHIFT_1: D_LSHIFT.1 D_Z.3 | length 27.8
  Top Layer w0.254: D_LSHIFT.1@27.35,27.44 50.94,27.44 52.06,28.56 D_Z.3@54.65,28.56
NetD_LSPACE_3: D_LSPACE.3 D_RSPACE.1 | length 59.3
  Top Layer w0.254: D_LSPACE.3@101.35,9.44 155.94,9.44 157.06,10.56 D_RSPACE.1@160.15,10.56
NetD_M_3: D_M.3 D_N.1 | length 16.8
  Top Layer w0.254: D_N.1@146.35,27.44 159.44,27.44 160.56,28.56 D_M.3@162.65,28.56
NetD_MUTE_1: D_MUTE.1 D_Num-.3 | length 32.1
  Top Layer w0.254: D_Num-.3@415.85,81.44 417.851,81.44 418.5,82.089 418.5,88.5 417.5,89.5 417.5,109 417.06,109.44 D_MUTE.1@415.85,109.44
NetD_MUTE_3: D_MUTE.3 D_VOL+.1 | length 16.8
  Top Layer w0.254: D_VOL+.1@397.85,109.44 397.91,109.5 411,109.5 412.06,110.56 D_MUTE.3@414.15,110.56
NetD_Num0_1: D_Num0.1 D_Right.3 | length 35.8
  Top Layer w0.254: D_Right.3@333.85,9.44 365.94,9.44 367.06,10.56 D_Num0.1@369.15,10.56
NetD_Num0_3: D_Num0.3 D_NumDot.1 | length 25.8
  Top Layer w0.254: D_Num0.3@370.85,9.44 393.94,9.44 395.06,10.56 D_NumDot.1@396.15,10.56
NetD_Num1_1: D_Num1.1 D_Num2.3 | length 16.8
  Top Layer w0.254: D_Num1.1@361.85,27.44 374.44,27.44 375.56,28.56 D_Num2.3@378.15,28.56
NetD_Num1_3: D_Num1.3 D_Num4.1 | length 31.8
  Top Layer w0.254: D_Num1.3@360.15,28.56 353.94,28.56 352.5,30 352.5,45.5 353.56,46.56 D_Num4.1@360.15,46.56
NetD_Num2_1: D_Num2.1 D_Num3.3 | length 16.8
  Top Layer w0.254: D_Num2.1@379.85,27.44 392.94,27.44 394.06,28.56 D_Num3.3@396.15,28.56
NetD_Num3_1: D_Num3.1 D_NumEnter.3 | length 31.2
  Top Layer w0.254: D_Num3.1@397.85,27.44 416.56,27.44 419,25 419,19.5 418,18.5 415.91,18.5 D_NumEnter.3@415.85,18.44
NetD_Num4_3: D_Num4.3 D_Num5.1 | length 16.8
  Top Layer w0.254: D_Num4.3@361.85,45.44 374.94,45.44 376.06,46.56 D_Num5.1@378.15,46.56
NetD_Num5_3: D_Num5.3 D_Num6.1 | length 16.8
  Top Layer w0.254: D_Num5.3@379.85,45.44 393.44,45.44 394.56,46.56 D_Num6.1@396.15,46.56
NetD_Num6_3: D_Num6.3 D_Num+.1 | length 25.8
  Top Layer w0.254: D_Num6.3@397.85,45.44 410.44,45.44 411,46 411,55 411.56,55.56 D_Num+.1@414.15,55.56
NetD_Num7_1: D_Num7.1 D_Num8.3 | length 16.8
  Top Layer w0.254: D_Num7.1@361.85,63.44 374.94,63.44 376.06,64.56 D_Num8.3@378.15,64.56
NetD_Num7_3: D_Num7.3 D_NumLock.1 | length 30.1
  Top Layer w0.254: D_Num7.3@360.15,64.56 354.44,64.56 353.5,65.5 353.5,81.5 354.56,82.56 D_NumLock.1@360.15,82.56
NetD_Num8_1: D_Num8.1 D_Num9.3 | length 16.8
  Top Layer w0.254: D_Num8.1@379.85,63.44 392.94,63.44 394.06,64.56 D_Num9.3@396.15,64.56
NetD_Num9_1: D_Num9.1 D_Num+.3 | length 30.8
  Top Layer w0.254: D_Num9.1@397.85,63.44 416.56,63.44 418.5,61.5 418.5,55 417.94,54.44 D_Num+.3@415.85,54.44
NetD_Num*_1: D_Num*.1 D_Num/.3 | length 16.8
  Top Layer w0.254: D_Num/.3@379.85,81.44 393.44,81.44 394.56,82.56 D_Num*.1@396.15,82.56
NetD_Num*_3: D_Num*.3 D_Num-.1 | length 16.8
  Top Layer w0.254: D_Num*.3@397.85,81.44 410.94,81.44 412.06,82.56 D_Num-.1@414.15,82.56
NetD_Num/_1: D_Num/.1 D_NumLock.3 | length 16.8
  Top Layer w0.254: D_NumLock.3@361.85,81.44 374.94,81.44 376.06,82.56 D_Num/.1@378.15,82.56
NetD_NumDot_3: D_NumDot.3 D_NumEnter.1 | length 25.8
  Top Layer w0.254: D_NumDot.3@397.85,9.44 409.44,9.44 410,10 410,19 410.56,19.56 D_NumEnter.1@414.15,19.56
NetD_O_1: D_O.1 D_P.3 | length 16.8
  Top Layer w0.254: D_O.1@186.85,63.44 199.94,63.44 201.06,64.56 D_P.3@203.15,64.56
NetD_PageDown_1: D_PageDown.1 D_PageUp.3 | length 21.7
  Top Layer w0.254: D_PageDown.1@333.85,63.44 335.69,63.44 336.5,64.25 336.5,70.5 335.5,71.5 335.5,80.5 334.56,81.44 D_PageUp.3@333.85,81.44
NetD_PauseBreak_1: D_PauseBreak.1 D_PLAY.3 | length 26.9
  Top Layer w0.254: D_PauseBreak.1@333.85,109.44 356.94,109.44 358,110.5 D_PLAY.3@360.328,110.5
NetD_PauseBreak_3: D_PauseBreak.3 D_ScrollLock.1 | length 16.5
  Top Layer w0.254: D_ScrollLock.1@315.85,109.44 328.94,109.44 330,110.5 D_PauseBreak.3@331.929,110.5
NetD_PLAY_1: D_PLAY.1 D_VOL-.3 | length 16.8
  Top Layer w0.254: D_PLAY.1@361.85,109.44 374.94,109.44 376.06,110.56 D_VOL-.3@378.15,110.56
NetD_PrintScreen_1: D_PrintScreen.1 D_ScrollLock.3 | length 16.8
  Top Layer w0.254: D_PrintScreen.1@297.85,109.44 310.94,109.44 312.06,110.56 D_ScrollLock.3@314.15,110.56
NetD_Q_1: D_Q.1 D_W.3 | length 16.8
  Top Layer w0.254: D_Q.1@42.85,63.44 55.44,63.44 56.56,64.56 D_W.3@59.15,64.56
NetD_Q_3: D_Q.3 D_TAB.1 | length 21.3
  Top Layer w0.254: D_TAB.1@20.35,63.44 37.94,63.44 39.06,64.56 D_Q.3@41.15,64.56
NetD_R_1: D_R.1 D_T.3 | length 16.8
  Top Layer w0.254: D_R.1@96.85,63.44 96.91,63.5 109.5,63.5 110.56,64.56 D_T.3@113.15,64.56
NetD_RALT_1: D_RALT.1 D_RSPACE.3 | length 37.3
  Top Layer w0.254: D_RSPACE.3@161.85,9.44 194.44,9.44 195.5,10.5 198.59,10.5 D_RALT.1@198.65,10.56
NetD_RALT_3: D_RALT.3 D_RWIN.1 | length 21.3
  Top Layer w0.254: D_RALT.3@200.35,9.44 217.44,9.44 218.56,10.56 D_RWIN.1@221.15,10.56
NetD_T_1: D_T.1 D_Y.3 | length 16.8
  Top Layer w0.254: D_T.1@114.85,63.44 127.44,63.44 128.56,64.56 D_Y.3@131.15,64.56
NetD_U_3: D_U.3 D_Y.1 | length 16.8
  Top Layer w0.254: D_Y.1@132.85,63.44 145.94,63.44 147.06,64.56 D_U.3@149.15,64.56
NetD_VOL+_3: D_VOL+.3 D_VOL-.1 | length 16.8
  Top Layer w0.254: D_VOL-.1@379.85,109.44 392.94,109.44 394.06,110.56 D_VOL+.3@396.15,110.56
NetD_X_3: D_X.3 D_Z.1 | length 16.8
  Top Layer w0.254: D_Z.1@56.35,27.44 69.44,27.44 70.56,28.56 D_X.3@72.65,28.56
NetJ1_2: J1.2 pad.3@302,43.5 R8.2 R10.1 SW1.2 | length 10.5
  Bottom Layer w0.254: R8.2@297.7,40 297.7,39 R10.1@298.25,38.45 300.5,38.45 SW1.2@300.55,38.5 300.55,39 300.923,39.373 301.873,39.373 302.5,40 J1.2@302.5,41.75 pad.3@302.5,43.5
NetJ2_2: J2.2 pad.3@300,30.75 R9.2 R11.1 SW2.2 | length 14
  Bottom Layer w0.254: R11.1@296.2,32.5 296.25,32.55 R9.2@296.25,34.8 300.25,34.8 SW2.2@300.55,34.5 300.55,34.141 300.923,33.768 301.732,33.768 302.5,33 J2.2@302.5,31.5 pad.3@299.5,31.5
NetR1_2: R1.2 X1.A5 | length 3.6
  Bottom Layer w0.254: R1.2@198.975,120.575 198.975,121.079 199.15,121.254 X1.A5@199.15,124.1
NetR2_2: R2.2 X1.B5 | length 3.9
  Bottom Layer w0.254: R2.2@202.075,121.05 202.375,120.75 R2.2@202.175,120.95 ; R2.2@202.15,120.875 202.15,121.025 X1.B5@202.15,124.1
NetR12_2: R12.2 R13.1 R14.1 | length 3.8
  Bottom Layer w0.254: R13.1@279,47.2 278.8,47.4 R12.2@278.8,49 278.8,50.6 R14.1@279,50.8
NetSW_0_1: SW_0.1 VD_24.1 | length 3.5
  Bottom Layer w0.254: VD_24.1@204,87.3 SW_0.1@204,90.8
NetSW_1_1: SW_1.1 VD_15.1 | length 3.5
  Bottom Layer w0.254: VD_15.1@42,87.3 SW_1.1@42,90.8
NetSW_2_1: SW_2.1 VD_16.1 | length 3.5
  Bottom Layer w0.254: VD_16.1@60,87.3 SW_2.1@60,90.8
NetSW_3_1: SW_3.1 VD_17.1 | length 3.5
  Bottom Layer w0.254: VD_17.1@78,87.3 SW_3.1@78,90.8
NetSW_4_1: SW_4.1 VD_18.1 | length 3.5
  Bottom Layer w0.254: VD_18.1@96,87.3 SW_4.1@96,90.8
NetSW_5_1: SW_5.1 VD_19.1 | length 3.5
  Bottom Layer w0.254: VD_19.1@114,87.3 SW_5.1@114,90.8
NetSW_6_1: SW_6.1 VD_20.1 | length 3.5
  Bottom Layer w0.254: VD_20.1@132,87.3 SW_6.1@132,90.8
NetSW_7_1: SW_7.1 VD_21.1 | length 3.5
  Bottom Layer w0.254: VD_21.1@150,87.3 SW_7.1@150,90.8
NetSW_8_1: SW_8.1 VD_22.1 | length 3.5
  Bottom Layer w0.254: VD_22.1@168,87.3 SW_8.1@168,90.8
NetSW_9_1: SW_9.1 VD_23.1 | length 3.5
  Bottom Layer w0.254: VD_23.1@186,87.3 SW_9.1@186,90.8
NetSW_'_1: SW_'.1 VD_53.1 | length 3.5
  Bottom Layer w0.254: VD_53.1@235.5,51.3 SW_'.1@235.5,54.8
NetSW_+_1: SW_+.1 VD_26.1 | length 3.5
  Bottom Layer w0.254: VD_26.1@240,87.3 SW_+.1@240,90.8
NetSW_-_1: SW_-.1 VD_25.1 | length 3.5
  Bottom Layer w0.254: VD_25.1@222,87.3 SW_-.1@222,90.8
NetSW_;_1: SW_;.1 VD_52.1 | length 3.5
  Bottom Layer w0.254: VD_52.1@217.5,51.3 217.5,54.8
NetSW_<_1: SW_<.1 VD_63.1 | length 3.5
  Bottom Layer w0.254: VD_63.1@190.5,33.3 SW_<.1@190.5,36.8
NetSW_>_1: SW_>.1 VD_64.1 | length 3.5
  Bottom Layer w0.254: VD_64.1@208.5,33.3 SW_>.1@208.5,36.8
NetSW_?_1: SW_?.1 VD_65.1 | length 3.5
  Bottom Layer w0.254: VD_65.1@226.5,33.3 SW_?.1@226.5,36.8
NetSW_[_1: SW_[.1 VD_39.1 | length 3.5
  Bottom Layer w0.254: VD_39.1@231,69.3 SW_[.1@231,72.8
NetSW_\_1: SW_\.1 VD_41.1 | length 3.5
  Bottom Layer w0.254: VD_41.1@272.5,69.3 SW_\.1@272.5,72.8
NetSW_]_1: SW_].1 VD_40.1 | length 3.5
  Bottom Layer w0.254: VD_40.1@249,69.3 SW_].1@249,72.8
NetSW_A_1: SW_A.1 VD_43.1 | length 3.5
  Bottom Layer w0.254: VD_43.1@55.5,51.3 SW_A.1@55.5,54.8
NetSW_B_1: SW_B.1 VD_60.1 | length 3.5
  Bottom Layer w0.254: VD_60.1@136.5,33.3 SW_B.1@136.5,36.8
NetSW_BACKSPACE_1: SW_BACKSPACE.1 VD_27.1 | length 3.2
  Bottom Layer w0.254: VD_27.1@267,87.6 SW_BACKSPACE.1@267,90.8
NetSW_C_1: SW_C.1 VD_58.1 | length 3.5
  Bottom Layer w0.254: VD_58.1@100.5,33.3 SW_C.1@100.5,36.8
NetSW_CAPSLOCK_1: SW_CAPSLOCK.1 VD_42.1 | length 3.6
  Bottom Layer w0.254: SW_CAPSLOCK.1@30.75,54.8 30.75,51.725 31,51.475 VD_42.1@31,51.3
NetSW_D_1: SW_D.1 VD_45.1 | length 3.5
  Bottom Layer w0.254: VD_45.1@91.5,51.3 SW_D.1@91.5,54.8
NetSW_Delete_1: SW_Delete.1 VD_90.1 | length 3.5
  Bottom Layer w0.254: VD_90.1@306,69.3 SW_Delete.1@306,72.8
NetSW_Down_1: SW_Down.1 VD_106.1 | length 3.5
  Bottom Layer w0.254: VD_106.1@324,15.3 SW_Down.1@324,18.8
NetSW_E_1: SW_E.1 VD_31.1 | length 3.5
  Bottom Layer w0.254: VD_31.1@87,69.3 SW_E.1@87,72.8
NetSW_End_1: SW_End.1 VD_91.1 | length 3.5
  Bottom Layer w0.254: VD_91.1@324,69.3 SW_End.1@324,72.8
NetSW_ENTER_1: SW_ENTER.1 VD_54.1 | length 3.6
  Bottom Layer w0.254: SW_ENTER.1@265.75,54.8 265.75,51.725 266,51.475 VD_54.1@266,51.3
NetSW_ESC_1: SW_ESC.1 VD_1.1 | length 3.5
  Bottom Layer w0.254: VD_1.1@24,115.3 SW_ESC.1@24,118.8
NetSW_F1_1: SW_F1.1 VD_2.1 | length 3.5
  Bottom Layer w0.254: VD_2.1@56,115.3 SW_F1.1@56,118.8
NetSW_F2_1: SW_F2.1 VD_3.1 | length 3.5
  Bottom Layer w0.254: VD_3.1@74,115.3 SW_F2.1@74,118.8
NetSW_F3_1: SW_F3.1 VD_4.1 | length 3.5
  Bottom Layer w0.254: VD_4.1@92,115.3 SW_F3.1@92,118.8
NetSW_F4_1: SW_F4.1 VD_5.1 | length 3.5
  Bottom Layer w0.254: VD_5.1@110,115.3 SW_F4.1@110,118.8
NetSW_F5_1: SW_F5.1 VD_6.1 | length 3.5
  Bottom Layer w0.254: VD_6.1@140,115.3 SW_F5.1@140,118.8
NetSW_F6_1: SW_F6.1 VD_7.1 | length 3.5
  Bottom Layer w0.254: VD_7.1@158,115.3 SW_F6.1@158,118.8
NetSW_F7_1: SW_F7.1 VD_8.1 | length 3.5
  Bottom Layer w0.254: VD_8.1@176,115.3 SW_F7.1@176,118.8
NetSW_F8_1: SW_F8.1 VD_9.1 | length 3.5
  Bottom Layer w0.254: VD_9.1@194,115.3 SW_F8.1@194,118.8
NetSW_F9_1: SW_F9.1 VD_10.1 | length 3.5
  Bottom Layer w0.254: VD_10.1@224,115.3 SW_F9.1@224,118.8
NetSW_F10_1: SW_F10.1 VD_11.1 | length 3.5
  Bottom Layer w0.254: VD_11.1@242,115.3 SW_F10.1@242,118.8
NetSW_F11_1: SW_F11.1 VD_12.1 | length 3.5
  Bottom Layer w0.254: VD_12.1@260,115.3 SW_F11.1@260,118.8
NetSW_F12_1: SW_F12.1 VD_13.1 | length 3.5
  Bottom Layer w0.254: VD_13.1@278,115.3 SW_F12.1@278,118.8
NetSW_F_1: SW_F.1 VD_46.1 | length 3.5
  Bottom Layer w0.254: VD_46.1@109.5,51.3 SW_F.1@109.5,54.8
NetSW_G_1: SW_G.1 VD_47.1 | length 3.5
  Bottom Layer w0.254: VD_47.1@127.5,51.3 SW_G.1@127.5,54.8
NetSW_H_1: SW_H.1 VD_48.1 | length 3.5
  Bottom Layer w0.254: VD_48.1@145.5,51.3 SW_H.1@145.5,54.8
NetSW_Home_1: SW_Home.1 VD_84.1 | length 3.5
  Bottom Layer w0.254: VD_84.1@324,87.3 SW_Home.1@324,90.8
NetSW_I_1: SW_I.1 VD_36.1 | length 3.5
  Bottom Layer w0.254: VD_36.1@177,69.3 SW_I.1@177,72.8
NetSW_Insert_1: SW_Insert.1 VD_83.1 | length 3.5
  Bottom Layer w0.254: VD_83.1@306,87.3 SW_Insert.1@306,90.8
NetSW_J_1: SW_J.1 VD_49.1 | length 3.5
  Bottom Layer w0.254: VD_49.1@163.5,51.3 SW_J.1@163.5,54.8
NetSW_K_1: SW_K.1 VD_50.1 | length 3.5
  Bottom Layer w0.254: VD_50.1@181.5,51.3 SW_K.1@181.5,54.8
NetSW_L_1: SW_L.1 VD_51.1 | length 3.5
  Bottom Layer w0.254: VD_51.1@199.5,51.3 SW_L.1@199.5,54.8
NetSW_LALT_1: SW_LALT.1 VD_69.1 | length 3.6
  Bottom Layer w0.254: VD_69.1@71,15.3 71,15.475 71.25,15.725 SW_LALT.1@71.25,18.8
NetSW_LCTRL_1: SW_LCTRL.1 VD_67.1 | length 3.6
  Bottom Layer w0.254: SW_LCTRL.1@26.25,18.8 26.25,15.725 26.5,15.475 VD_67.1@26.5,15.3
NetSW_Left_1: SW_Left.1 VD_105.1 | length 3.5
  Bottom Layer w0.254: VD_105.1@306,15.3 SW_Left.1@306,18.8
NetSW_LIST_1: SW_LIST.1 VD_74.1 | length 3.6
  Bottom Layer w0.254: SW_LIST.1@253.25,18.8 253.25,15.725 253.5,15.475 VD_74.1@253.5,15.3
NetSW_LSHIFT_1: SW_LSHIFT.1 VD_55.1 | length 3.6
  Bottom Layer w0.254: SW_LSHIFT.1@35.25,36.8 35.25,33.725 35.5,33.475 VD_55.1@35.5,33.3
NetSW_LSPACE_1: SW_LSPACE.1 VD_70.1 | length 3.5
  Bottom Layer w0.254: VD_70.1@109.5,15.3 SW_LSPACE.1@109.5,18.8
NetSW_LWIN_1: SW_LWIN.1 VD_68.1 | length 3.6
  Bottom Layer w0.254: SW_LWIN.1@48.75,18.8 48.75,15.725 49,15.475 VD_68.1@49,15.3
NetSW_M_1: SW_M.1 VD_62.1 | length 3.5
  Bottom Layer w0.254: VD_62.1@172.5,33.3 SW_M.1@172.5,36.8
NetSW_MUTE_1: SW_MUTE.1 VD_82.1 | length 3.5
  Bottom Layer w0.254: VD_82.1@424,115.3 SW_MUTE.1@424,118.8
NetSW_N_1: SW_N.1 VD_61.1 | length 3.5
  Bottom Layer w0.254: VD_61.1@154.5,33.3 SW_N.1@154.5,36.8
NetSW_Num0_1: SW_Num0.1 VD_108.1 | length 3.5
  Bottom Layer w0.254: VD_108.1@379,15.3 SW_Num0.1@379,18.8
NetSW_Num1_1: SW_Num1.1 VD_101.1 | length 3.5
  Bottom Layer w0.254: VD_101.1@370,33.3 SW_Num1.1@370,36.8
NetSW_Num2_1: SW_Num2.1 VD_102.1 | length 3.5
  Bottom Layer w0.254: VD_102.1@388,33.3 SW_Num2.1@388,36.8
NetSW_Num3_1: SW_Num3.1 VD_103.1 | length 3.5
  Bottom Layer w0.254: VD_103.1@406,33.3 SW_Num3.1@406,36.8
NetSW_Num4_1: SW_Num4.1 VD_97.1 | length 3.5
  Bottom Layer w0.254: VD_97.1@370,51.3 SW_Num4.1@370,54.8
NetSW_Num5_1: SW_Num5.1 VD_98.1 | length 3.5
  Bottom Layer w0.254: VD_98.1@388,51.3 SW_Num5.1@388,54.8
NetSW_Num6_1: SW_Num6.1 VD_99.1 | length 3.5
  Bottom Layer w0.254: VD_99.1@406,51.3 SW_Num6.1@406,54.8
NetSW_Num7_1: SW_Num7.1 VD_93.1 | length 3.5
  Bottom Layer w0.254: VD_93.1@370,69.3 SW_Num7.1@370,72.8
NetSW_Num8_1: SW_Num8.1 VD_94.1 | length 3.5
  Bottom Layer w0.254: VD_94.1@388,69.3 SW_Num8.1@388,72.8
NetSW_Num9_1: SW_Num9.1 VD_95.1 | length 3.5
  Bottom Layer w0.254: VD_95.1@406,69.3 SW_Num9.1@406,72.8
NetSW_Num*_1: SW_Num*.1 VD_88.1 | length 3.5
  Bottom Layer w0.254: VD_88.1@406,87.3 SW_Num*.1@406,90.8
NetSW_Num+_1: SW_Num+.1 VD_96.1 | length 3.5
  Bottom Layer w0.254: VD_96.1@424,60.3 SW_Num+.1@424,63.8
NetSW_Num-_1: SW_Num-.1 VD_89.1 | length 3.5
  Bottom Layer w0.254: VD_89.1@424,87.3 SW_Num-.1@424,90.8
NetSW_Num/_1: SW_Num/.1 VD_87.1 | length 3.5
  Bottom Layer w0.254: VD_87.1@388,87.3 388,90.826 SW_Num/.1@388.003,90.829
NetSW_NumDot_1: SW_NumDot.1 VD_109.1 | length 3.5
  Bottom Layer w0.254: VD_109.1@406,15.3 406,18.826 SW_NumDot.1@406.003,18.829
NetSW_NumEnter_1: SW_NumEnter.1 VD_104.1 | length 3.5
  Bottom Layer w0.254: VD_104.1@424,24.3 SW_NumEnter.1@424,27.8
NetSW_NumLock_1: SW_NumLock.1 VD_86.1 | length 3.5
  Bottom Layer w0.254: VD_86.1@370,87.3 SW_NumLock.1@370,90.8
NetSW_O_1: SW_O.1 VD_37.1 | length 3.5
  Bottom Layer w0.254: VD_37.1@195,69.3 SW_O.1@195,72.8
NetSW_P_1: SW_P.1 VD_38.1 | length 3.5
  Bottom Layer w0.254: VD_38.1@213,69.3 SW_P.1@213,72.8
NetSW_PageDown_1: SW_PageDown.1 VD_92.1 | length 3.5
  Bottom Layer w0.254: VD_92.1@342,69.3 SW_PageDown.1@342,72.8
NetSW_PageUp_1: SW_PageUp.1 VD_85.1 | length 3.5
  Bottom Layer w0.254: VD_85.1@342,87.3 SW_PageUp.1@342,90.8
NetSW_PauseBreak_1: SW_PauseBreak.1 VD_78.1 | length 3.5
  Bottom Layer w0.254: VD_78.1@342,115.3 SW_PauseBreak.1@342,118.8
NetSW_PLAY_1: SW_PLAY.1 VD_79.1 | length 3.5
  Bottom Layer w0.254: VD_79.1@370,115.3 SW_PLAY.1@370,118.8
NetSW_PrintScreen_1: SW_PrintScreen.1 VD_76.1 | length 3.5
  Bottom Layer w0.254: VD_76.1@306,115.3 SW_PrintScreen.1@306,118.8
NetSW_Q_1: SW_Q.1 VD_29.1 | length 3.5
  Bottom Layer w0.254: VD_29.1@51,69.3 SW_Q.1@51,72.8
NetSW_R_1: SW_R.1 VD_32.1 | length 3.5
  Bottom Layer w0.254: VD_32.1@105,69.3 SW_R.1@105,72.8
NetSW_RALT_1: SW_RALT.1 VD_72.1 | length 3.6
  Bottom Layer w0.254: SW_RALT.1@208.25,18.8 208.25,15.725 208.5,15.475 VD_72.1@208.5,15.3
NetSW_RCTRL_1: SW_RCTRL.1 VD_75.1 | length 3.6
  Bottom Layer w0.254: VD_75.1@275.5,15.3 275.5,15.475 275.75,15.725 SW_RCTRL.1@275.75,18.8
NetSW_Right_1: SW_Right.1 VD_107.1 | length 3.5
  Bottom Layer w0.254: VD_107.1@342,15.3 SW_Right.1@342,18.8
NetSW_RSHIFT_1: SW_RSHIFT.1 VD_66.1 | length 3.6
  Bottom Layer w0.254: SW_RSHIFT.1@261.25,36.8 261.25,33.725 261.5,33.475 VD_66.1@261.5,33.3
NetSW_RSPACE_1: SW_RSPACE.1 VD_71.1 | length 3.5
  Bottom Layer w0.254: VD_71.1@170,15.3 SW_RSPACE.1@170,18.8
NetSW_RWIN_1: SW_RWIN.1 VD_73.1 | length 3.6
  Bottom Layer w0.254: VD_73.1@230.5,15.3 230.5,15.475 230.75,15.725 SW_RWIN.1@230.75,18.8
NetSW_S_1: SW_S.1 VD_44.1 | length 3.5
  Bottom Layer w0.254: VD_44.1@73.5,51.3 SW_S.1@73.5,54.8
NetSW_ScrollLock_1: SW_ScrollLock.1 VD_77.1 | length 3.5
  Bottom Layer w0.254: VD_77.1@324,115.3 SW_ScrollLock.1@324,118.8
NetSW_T_1: SW_T.1 VD_33.1 | length 3.5
  Bottom Layer w0.254: VD_33.1@123,69.3 SW_T.1@123,72.8
NetSW_TAB_1: SW_TAB.1 VD_28.1 | length 3.5
  Bottom Layer w0.254: VD_28.1@28.5,69.3 SW_TAB.1@28.5,72.8
NetSW_U_1: SW_U.1 VD_35.1 | length 3.5
  Bottom Layer w0.254: VD_35.1@159,69.3 SW_U.1@159,72.8
NetSW_Up_1: SW_Up.1 VD_100.1 | length 3.5
  Bottom Layer w0.254: VD_100.1@324,33.3 SW_Up.1@324,36.8
NetSW_V_1: SW_V.1 VD_59.1 | length 3.5
  Bottom Layer w0.254: VD_59.1@118.5,33.3 SW_V.1@118.5,36.8
NetSW_VOL+_1: SW_VOL+.1 VD_81.1 | length 3.5
  Bottom Layer w0.254: VD_81.1@406,115.3 SW_VOL+.1@406,118.8
NetSW_VOL_-_1: SW_VOL_-.1 VD_80.1 | length 3.5
  Bottom Layer w0.254: VD_80.1@388,115.3 SW_VOL_-.1@388,118.8
NetSW_W_1: SW_W.1 VD_30.1 | length 3.5
  Bottom Layer w0.254: VD_30.1@69,69.3 SW_W.1@69,72.8
NetSW_X_1: SW_X.1 VD_57.1 | length 3.5
  Bottom Layer w0.254: VD_57.1@82.5,33.3 SW_X.1@82.5,36.8
NetSW_Y_1: SW_Y.1 VD_34.1 | length 3.5
  Bottom Layer w0.254: VD_34.1@141,69.3 SW_Y.1@141,72.8
NetSW_Z_1: SW_Z.1 VD_56.1 | length 3.5
  Bottom Layer w0.254: VD_56.1@64.5,33.3 SW_Z.1@64.5,36.8
NetSW_~_1: SW_~.1 VD_14.1 | length 3.5
  Bottom Layer w0.254: VD_14.1@24,87.3 SW_~.1@24,90.8
RESET: C118.2 D1.7 pad.3@303.75,53.25 R7.1 SW3.1 | length 19
  Top Layer w0.254: v1(299.5,47.25) v1(299.5,49.75)
  Bottom Layer w0.254: D1.7@296.2,47.75 299,47.75 v1(299.5,47.25) ; v1(299.5,49.75) 299.5,53.25 300.652,54.402 300.652,54.952 R7.1@300.95,55.25 C118.2@302.8,55.25 302.75,55.2 302.75,54.25 303.25,53.75 SW3.1@306.55,53.75
Row_1: D1.38 SW_ESC.2 SW_F1.2 SW_F2.2 SW_F3.2 SW_F4.2 SW_F5.2 SW_F6.2 SW_F7.2 SW_F8.2 SW_F9.2 SW_F10.2 SW_F11.2 SW_F12.2 SW_MUTE.2 SW_PauseBreak.2 SW_PLAY.2 SW_PrintScreen.2 SW_ScrollLock.2 SW_VOL+.2 SW_VOL_-.2 | length 531.6
  Top Layer w0.254: v1(180.991,128.036) 181.027,128 v1@211,128
  Bottom Layer w0.254: SW_ESC.2@11,121 11,123.351 11.149,123.5 43,123.5 ; SW_F1.2@43,121 43,123.5 ; SW_F2.2@61,121 61,123.5 ; SW_F3.2@79,121 79,123.5 ; SW_F4.2@97,121 97,123.5 ; SW_F5.2@127,121 127,123.5 ; SW_F6.2@145,121 145,123.5 ; SW_F7.2@163,121 163,123.5 ; SW_F8.2@181,121 181,123.351 ; v1@181,128 181,123.351 ; v1(210.991,128.036) 211,128.027 211,123.351 ; SW_F9.2@211,121 211,123.351 ; SW_F10.2@229,121 229,123.5 ; SW_F11.2@247,121 247,123.5 ; SW_F12.2@265,121 265,123.5 ; D1.38@289.75,52.2 289.75,60.75 290.75,61.75 290.75,67.5 288.75,69.5 288.75,123.5 ; SW_PrintScreen.2@293,121 293,123.5 ; SW_ScrollLock.2@311,121 311,123.5 ; SW_PauseBreak.2@329,121 329,123.5 ; SW_PLAY.2@357,121 357,123.5 ; SW_VOL_-.2@375,121 375,123.5 ; SW_VOL+.2@393,121 393,123.5 ; SW_MUTE.2@411,121 411,123.351 410.851,123.5 393,123.5 ; 43,123.5 61,123.5 ; 61,123.5 79,123.5 ; 79,123.5 97,123.5 ; 97,123.5 127,123.5 ; 127,123.5 145,123.5 ; 145,123.5 163,123.5 ; 163,123.5 180.851,123.5 181,123.351 ; 211,123.351 211.149,123.5 229,123.5 ; 229,123.5 247,123.5 ; 247,123.5 265,123.5 ; 265,123.5 288.75,123.5 ; 288.75,123.5 293,123.5 ; 293,123.5 311,123.5 ; 311,123.5 329,123.5 ; 329,123.5 357,123.5 ; 357,123.5 375,123.5 ; 375,123.5 393,123.5
Row_2: D1.39 SW_0.2 SW_1.2 SW_2.2 SW_3.2 SW_4.2 SW_5.2 SW_6.2 SW_7.2 SW_8.2 SW_9.2 SW_+.2 SW_-.2 SW_Home.2 SW_Insert.2 SW_Num*.2 SW_Num-.2 SW_Num/.2 SW_NumLock.2 SW_PageUp.2 SW_~.2 | length 501.1
  Top Layer w0.254: v1(274.491,97.036) 274.527,97 v1(289.5,97)
  Bottom Layer w0.254: SW_~.2@11,93 11,95.351 11.149,95.5 29,95.5 ; SW_1.2@29,93 29,95.5 ; SW_2.2@47,93 47,95.5 ; SW_3.2@65,93 65,95.5 ; SW_4.2@83,93 83,95.5 ; SW_5.2@101,93 101,95.5 ; SW_6.2@119,93 119,95.5 ; SW_7.2@137,93 137,95.5 ; SW_8.2@155,93 155,95.5 ; 172.889,95.457 173,95.346 SW_9.2@173,93 ; SW_0.2@191,93 191,95.426 190.926,95.5 ; SW_-.2@209,93 209,95.5 ; SW_+.2@227,93 227,95.351 ; v1@274.5,97 273.5,98 228,98 227,97 227,95.351 ; D1.39@290.25,52.2 290.25,60.25 291.5,61.5 291.5,65.5 293,67 293,71 289.5,74.5 v1(289.5,97) 292.851,97 293,96.851 293,95.351 ; SW_Insert.2@293,93 293,95.351 ; SW_Home.2@311,93 311,95.5 ; SW_PageUp.2@329,93 329,95.5 ; SW_NumLock.2@357,93 357,95.5 ; SW_Num/.2@375.003,93.029 375.003,95.497 375,95.5 ; SW_Num*.2@393,93 393,95.5 ; SW_Num-.2@411,93 411,95.351 410.851,95.5 393,95.5 ; 29,95.5 47,95.5 ; 47,95.5 65,95.5 ; 65,95.5 83,95.5 ; 83,95.5 101,95.5 ; 101,95.5 119,95.5 ; 119,95.5 137,95.5 ; 137,95.5 155,95.5 ; 155,95.5 190.926,95.5 ; 190.926,95.5 209,95.5 ; 209,95.5 226.851,95.5 227,95.351 ; 293,95.351 293.149,95.5 311,95.5 ; 311,95.5 329,95.5 ; 329,95.5 357,95.5 ; 357,95.5 375,95.5 ; 375,95.5 393,95.5
Row_3: D1.40 SW_[.2 SW_].2 SW_Delete.2 SW_E.2 SW_End.2 SW_I.2 SW_Num7.2 SW_Num8.2 SW_Num9.2 SW_Num+.2 SW_O.2 SW_P.2 SW_PageDown.2 SW_Q.2 SW_R.2 SW_T.2 SW_TAB.2 SW_U.2 SW_W.2 SW_Y.2 | length 479.2
  Top Layer w0.254: v1(242.491,77.536) 242.527,77.5 v1@264.5,77.5 ; v1(274.947,77.55) 274.996,77.5 v1(290.25,77.5)
  Bottom Layer w0.254: SW_TAB.2@15.5,75 15.5,77.351 15.649,77.5 38,77.5 ; SW_Q.2@38,75 38,77.5 ; SW_W.2@56,75 56,77.5 ; SW_E.2@74,75 74,77.5 ; SW_R.2@92,75 92,77.5 ; SW_T.2@110,75 110,77.5 ; SW_Y.2@128,75 128,77.5 ; SW_U.2@146,75 146,77.5 ; SW_I.2@164,75 164,77.5 ; SW_O.2@182,75 182,77.5 ; SW_P.2@200,75 200,77.5 ; SW_[.2@218,75 218,77.5 ; SW_].2@236,75 236,77.351 235.851,77.5 ; v1@242.5,77.5 235.851,77.5 ; v1(264.491,77.536) 264.527,77.5 v1@275,77.5 ; v1(290.25,77.5) 311.074,77.5 ; D1.40@290.75,52.2 290.75,60 292.25,61.5 292.25,65 294,66.75 294,72 293,73 SW_Delete.2@293,75 293,77.351 293.149,77.5 ; SW_End.2@311,75 311,77.426 311.074,77.5 ; SW_PageDown.2@329,75 329,77.5 ; SW_Num7.2@357,75 357,77.5 ; SW_Num8.2@375,75 375,77.5 ; SW_Num9.2@393,75 393,77.351 392.851,77.5 ; SW_Num+.2@411,66 411,77.351 410.851,77.5 392.851,77.5 ; 38,77.5 56,77.5 ; 56,77.5 74,77.5 ; 74,77.5 92,77.5 ; 92,77.5 110,77.5 ; 110,77.5 128,77.5 ; 128,77.5 146,77.5 ; 146,77.5 164,77.5 ; 164,77.5 182,77.5 ; 182,77.5 200,77.5 ; 200,77.5 218,77.5 ; 218,77.5 235.851,77.5 ; 311.074,77.5 329,77.5 ; 329,77.5 357,77.5 ; 357,77.5 375,77.5 ; 375,77.5 392.851,77.5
